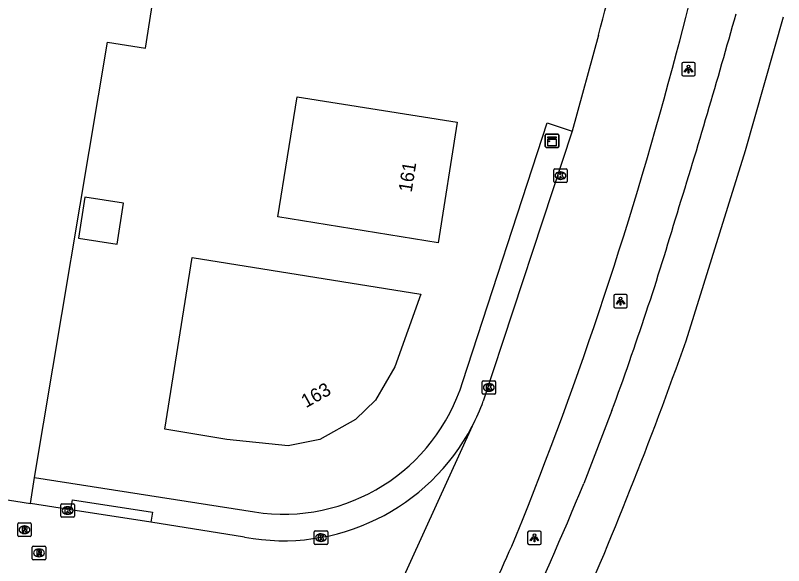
# Model space of a CAD drawing. Extents: x 154324 to 155743, y 382939 to 384183.
# Drawn here: x 155324.9 to 155381.7, y 383215.2 to 383256 of the extents above; entities that cross this region are included whole.
import ezdxf

# ---------------------------------------------------------------- set-up
doc = ezdxf.new("R2010")
doc.units = 0
for name, color, linetype in [('IMGEO_Fietspad_gesloten', 7, 'Continuous'), ('IMGEO_Groenvoorziening', 7, 'Continuous'), ('IMGEO_Kast', 7, 'Continuous'), ('IMGEO_Kolk', 7, 'Continuous'), ('IMGEO_Lichtpunt', 7, 'Continuous'), ('IMGEO_Pand', 7, 'Continuous'), ('IMGEO_Pand_nummerreeks', 7, 'Continuous'), ('IMGEO_Rijbaan_lokaal_gesloten', 7, 'Continuous'), ('IMGEO_Rijbaan_lokaal_open', 7, 'Continuous'), ('IMGEO_Rioolput', 7, 'Continuous'), ('IMGEO_Voetpad_open', 7, 'Continuous')]:
    doc.layers.add(name, color=color, linetype=linetype)

msp = doc.modelspace()

# ---------------------------------------------------------------- linework, layer by layer
at = {"layer": 'IMGEO_Fietspad_gesloten'}
for points in [[(155374.508, 383231.879), (155378.906, 383245.985), (155381.726, 383255.864)], [(155369.018, 383226.725), (155366.938, 383221.324)]]:
    msp.add_lwpolyline(points, dxfattribs=at)
for centre, radius, start, end in [((154859.102, 383401.381), 539.053, 342.73246, 344.36555), ((155146.238, 383308.495), 237.313, 339.84457, 343.56976), ((155076.293, 383337.641), 316.414, 336.21083, 340.473), ((155093.167, 383334.857), 296.379, 335.03919, 337.47613)]:
    msp.add_arc(centre, radius, start, end, dxfattribs=at)
at = {"layer": 'IMGEO_Groenvoorziening'}
msp.add_lwpolyline([(155326.27, 383221.771), (155331.676, 383253.994), (155334.487, 383253.554), (155341.319, 383297.286)], dxfattribs=at)
at = {"layer": 'IMGEO_Kast'}
for p, q in [((155364.086, 383246.27), (155364.086, 383247.111)), ((155364.086, 383247.111), (155364.086, 383246.27)), ((155364.161, 383247.195), (155365.002, 383247.195)), ((155365.002, 383247.195), (155364.161, 383247.195)), ((155365.086, 383247.12), (155365.086, 383246.279)), ((155365.086, 383246.279), (155365.086, 383247.12)), ((155365.011, 383246.195), (155364.17, 383246.195)), ((155364.17, 383246.195), (155365.011, 383246.195))]:
    msp.add_line(p, q, dxfattribs=at)
for points in [[(155364.281, 383246.985), (155364.881, 383246.985), (155364.881, 383246.9), (155364.281, 383246.9), (155364.281, 383246.985)], [(155364.281, 383246.81), (155364.881, 383246.81), (155364.881, 383246.321), (155364.281, 383246.321), (155364.281, 383246.81)]]:
    msp.add_lwpolyline(points, dxfattribs=at)
msp.add_circle((155364.365, 383246.659), 0.0377, dxfattribs=at)
for centre, start, end in [((155364.164, 383247.117), 92.4484, 184.2845), ((155364.164, 383247.117), 92.4484, 184.2845), ((155365.008, 383247.117), 2.4484, 94.2845), ((155365.008, 383247.117), 2.4484, 94.2845), ((155364.164, 383246.273), 182.4484, 274.2845), ((155364.164, 383246.273), 182.4484, 274.2845), ((155365.008, 383246.273), 272.4484, 4.2845), ((155365.008, 383246.273), 272.4484, 4.2845)]:
    msp.add_arc(centre, 0.0779, start, end, dxfattribs=at)
at = {"layer": 'IMGEO_Kolk'}
for p, q in [((155364.708, 383243.689), (155364.708, 383244.541)), ((155364.783, 383244.615), (155365.635, 383244.615)), ((155365.709, 383244.541), (155365.709, 383243.689)), ((155365.196, 383244.395), (155365.221, 383244.395)), ((155365.635, 383243.615), (155364.783, 383243.615)), ((155365.219, 383243.835), (155365.194, 383243.835)), ((155359.407, 383228.001), (155359.407, 383228.853)), ((155359.482, 383228.927), (155360.334, 383228.927)), ((155359.895, 383228.707), (155359.92, 383228.707)), ((155360.408, 383228.853), (155360.408, 383228.001)), ((155359.918, 383228.147), (155359.893, 383228.147)), ((155360.334, 383227.927), (155359.482, 383227.927)), ((155328.233, 383218.892), (155328.233, 383219.744)), ((155328.308, 383219.818), (155329.16, 383219.818)), ((155328.721, 383219.598), (155328.746, 383219.598)), ((155329.234, 383219.744), (155329.234, 383218.892)), ((155328.744, 383219.038), (155328.719, 383219.038)), ((155329.16, 383218.818), (155328.308, 383218.818)), ((155346.981, 383216.884), (155346.981, 383217.736)), ((155347.056, 383217.81), (155347.908, 383217.81)), ((155347.982, 383217.736), (155347.982, 383216.884)), ((155347.469, 383217.59), (155347.494, 383217.59)), ((155347.908, 383216.81), (155347.056, 383216.81)), ((155347.492, 383217.03), (155347.467, 383217.03))]:
    msp.add_line(p, q, dxfattribs=at)
for points in [[(155364.708, 383243.689), (155364.708, 383244.541)], [(155364.783, 383244.615), (155365.635, 383244.615)], [(155365.709, 383244.541), (155365.709, 383243.689)], [(155365.029, 383244.315), (155365.152, 383244.315), (155365.152, 383244.164), (155365.282, 383244.315), (155365.446, 383244.315), (155365.3, 383244.164), (155365.453, 383243.915), (155365.301, 383243.915), (155365.216, 383244.079), (155365.152, 383244.012), (155365.152, 383243.915), (155365.029, 383243.915), (155365.029, 383244.315)], [(155365.635, 383243.615), (155364.783, 383243.615)], [(155359.407, 383228.001), (155359.407, 383228.853)], [(155359.482, 383228.927), (155360.334, 383228.927)], [(155359.728, 383228.627), (155359.851, 383228.627), (155359.851, 383228.476), (155359.981, 383228.627), (155360.145, 383228.627), (155359.999, 383228.476), (155360.152, 383228.227), (155360, 383228.227), (155359.915, 383228.391), (155359.851, 383228.324), (155359.851, 383228.227), (155359.728, 383228.227), (155359.728, 383228.627)], [(155360.408, 383228.853), (155360.408, 383228.001)], [(155360.334, 383227.927), (155359.482, 383227.927)], [(155328.233, 383218.892), (155328.233, 383219.744)], [(155328.308, 383219.818), (155329.16, 383219.818)], [(155328.554, 383219.518), (155328.677, 383219.518), (155328.677, 383219.367), (155328.807, 383219.518), (155328.971, 383219.518), (155328.825, 383219.367), (155328.978, 383219.118), (155328.826, 383219.118), (155328.741, 383219.282), (155328.677, 383219.215), (155328.677, 383219.118), (155328.554, 383219.118), (155328.554, 383219.518)], [(155329.234, 383219.744), (155329.234, 383218.892)], [(155329.16, 383218.818), (155328.308, 383218.818)], [(155346.981, 383216.884), (155346.981, 383217.736)], [(155347.056, 383217.81), (155347.908, 383217.81)], [(155347.982, 383217.736), (155347.982, 383216.884)], [(155347.302, 383217.51), (155347.425, 383217.51), (155347.425, 383217.359), (155347.555, 383217.51), (155347.719, 383217.51), (155347.573, 383217.359), (155347.726, 383217.11), (155347.574, 383217.11), (155347.489, 383217.274), (155347.425, 383217.207), (155347.425, 383217.11), (155347.302, 383217.11), (155347.302, 383217.51)], [(155347.908, 383216.81), (155347.056, 383216.81)]]:
    msp.add_lwpolyline(points, dxfattribs=at)
for centre, start, end in [((155364.785, 383244.539), 91.552, 178.448), ((155364.785, 383244.539), 91.552, 178.448), ((155365.633, 383244.539), 1.552, 88.448), ((155365.633, 383244.539), 1.552, 88.448), ((155364.785, 383243.691), 181.552, 268.448), ((155364.785, 383243.691), 181.552, 268.448), ((155365.633, 383243.691), 271.552, 358.448), ((155365.633, 383243.691), 271.552, 358.448), ((155359.484, 383228.851), 91.552, 178.448), ((155359.484, 383228.851), 91.552, 178.448), ((155360.332, 383228.851), 1.552, 88.448), ((155360.332, 383228.851), 1.552, 88.448), ((155359.484, 383228.003), 181.552, 268.448), ((155359.484, 383228.003), 181.552, 268.448), ((155360.332, 383228.003), 271.552, 358.448), ((155360.332, 383228.003), 271.552, 358.448), ((155328.31, 383219.742), 91.552, 178.448), ((155328.31, 383219.742), 91.552, 178.448), ((155329.158, 383219.742), 1.552, 88.448), ((155329.158, 383219.742), 1.552, 88.448), ((155328.31, 383218.894), 181.552, 268.448), ((155328.31, 383218.894), 181.552, 268.448), ((155329.158, 383218.894), 271.552, 358.448), ((155329.158, 383218.894), 271.552, 358.448), ((155347.058, 383217.734), 91.552, 178.448), ((155347.058, 383217.734), 91.552, 178.448), ((155347.906, 383217.734), 1.552, 88.448), ((155347.906, 383217.734), 1.552, 88.448), ((155347.058, 383216.886), 181.552, 268.448), ((155347.058, 383216.886), 181.552, 268.448), ((155347.906, 383216.886), 271.552, 358.448), ((155347.906, 383216.886), 271.552, 358.448)]:
    msp.add_arc(centre, 0.0765, start, end, dxfattribs=at)
for centre, major_axis, ratio, start_param, end_param in [((155365.195, 383244.115), (-0.387, 0.002), 0.722429, 4.712389, 7.853982), ((155365.22, 383244.115), (-0.39, 0.002), 0.717154, 1.570796, 4.712389), ((155359.894, 383228.427), (-0.387, 0.002), 0.722429, 4.712389, 7.853982), ((155359.919, 383228.427), (-0.39, 0.002), 0.717154, 1.570796, 4.712389), ((155328.72, 383219.318), (-0.387, 0.002), 0.722429, 4.712389, 7.853982), ((155328.745, 383219.318), (-0.39, 0.002), 0.717154, 1.570796, 4.712389), ((155347.468, 383217.31), (-0.387, 0.002), 0.722429, 4.712389, 7.853982), ((155347.493, 383217.31), (-0.39, 0.002), 0.717154, 1.570796, 4.712389)]:
    msp.add_ellipse(centre, major_axis=major_axis, ratio=ratio, start_param=start_param, end_param=end_param, dxfattribs=at)
at = {"layer": 'IMGEO_Lichtpunt'}
for p, q in [((155375.087, 383252.498), (155374.279, 383252.498)), ((155375.087, 383252.498), (155374.279, 383252.498)), ((155374.185, 383252.403), (155374.185, 383251.596)), ((155374.185, 383252.403), (155374.185, 383251.596)), ((155375.181, 383251.596), (155375.181, 383252.403)), ((155375.181, 383251.596), (155375.181, 383252.403)), ((155374.279, 383251.502), (155375.087, 383251.502)), ((155374.279, 383251.502), (155375.087, 383251.502)), ((155369.156, 383235.228), (155369.156, 383234.421)), ((155369.156, 383235.228), (155369.156, 383234.421)), ((155370.058, 383235.323), (155369.25, 383235.323)), ((155370.058, 383235.323), (155369.25, 383235.323)), ((155370.152, 383234.421), (155370.152, 383235.228)), ((155370.152, 383234.421), (155370.152, 383235.228)), ((155369.25, 383234.327), (155370.058, 383234.327)), ((155369.25, 383234.327), (155370.058, 383234.327)), ((155363.681, 383217.798), (155362.873, 383217.798)), ((155363.681, 383217.798), (155362.873, 383217.798)), ((155362.779, 383217.703), (155362.779, 383216.896)), ((155362.779, 383217.703), (155362.779, 383216.896)), ((155363.775, 383216.896), (155363.775, 383217.703)), ((155363.775, 383216.896), (155363.775, 383217.703)), ((155362.873, 383216.802), (155363.681, 383216.802)), ((155362.873, 383216.802), (155363.681, 383216.802))]:
    msp.add_line(p, q, dxfattribs=at)
for points in [[(155374.559, 383252.067), (155374.598, 383252.039), (155374.41, 383251.777), (155374.372, 383251.804), (155374.559, 383252.067)], [(155374.661, 383252.019), (155374.708, 383252.019), (155374.708, 383251.697), (155374.661, 383251.697), (155374.661, 383252.019)], [(155374.771, 383252.039), (155374.809, 383252.066), (155374.996, 383251.804), (155374.957, 383251.776), (155374.771, 383252.039)], [(155369.53, 383234.892), (155369.569, 383234.864), (155369.381, 383234.602), (155369.343, 383234.629), (155369.53, 383234.892)], [(155369.632, 383234.844), (155369.679, 383234.844), (155369.679, 383234.522), (155369.632, 383234.522), (155369.632, 383234.844)], [(155369.742, 383234.864), (155369.78, 383234.891), (155369.967, 383234.629), (155369.928, 383234.601), (155369.742, 383234.864)], [(155363.153, 383217.367), (155363.192, 383217.339), (155363.004, 383217.077), (155362.966, 383217.104), (155363.153, 383217.367)], [(155363.255, 383217.319), (155363.302, 383217.319), (155363.302, 383216.997), (155363.255, 383216.997), (155363.255, 383217.319)], [(155363.365, 383217.339), (155363.403, 383217.366), (155363.59, 383217.104), (155363.551, 383217.076), (155363.365, 383217.339)]]:
    msp.add_lwpolyline(points, dxfattribs=at)
for centre in [(155374.684, 383252.201), (155369.655, 383235.026), (155363.278, 383217.501)]:
    msp.add_circle(centre, 0.0994, dxfattribs=at)
for centre, start, end in [((155374.279, 383252.403), 90, 180), ((155374.279, 383252.403), 90, 180), ((155375.087, 383252.403), 0, 90), ((155375.087, 383252.403), 0, 90), ((155374.279, 383251.596), 180, 270), ((155374.279, 383251.596), 180, 270), ((155375.087, 383251.596), 270, 0), ((155375.087, 383251.596), 270, 360), ((155369.25, 383235.228), 90, 180), ((155369.25, 383235.228), 90, 180), ((155370.058, 383235.228), 0, 90), ((155370.058, 383235.228), 0, 90), ((155369.25, 383234.421), 180, 270), ((155369.25, 383234.421), 180, 270), ((155370.058, 383234.421), 270, 0), ((155370.058, 383234.421), 270, 360), ((155362.873, 383217.703), 90, 180), ((155362.873, 383217.703), 90, 180), ((155363.681, 383217.703), 0, 90), ((155363.681, 383217.703), 0, 90), ((155362.873, 383216.896), 180, 270), ((155362.873, 383216.896), 180, 270), ((155363.681, 383216.896), 270, 0), ((155363.681, 383216.896), 270, 360)]:
    msp.add_arc(centre, 0.0946, start, end, dxfattribs=at)
at = {"layer": 'IMGEO_Pand'}
for points in [[(155357.573, 383248.067), (155356.157, 383239.149), (155344.285, 383241.069), (155345.717, 383249.958), (155357.573, 383248.067)], [(155329.989, 383242.521), (155329.521, 383239.482), (155332.387, 383239.041), (155332.855, 383242.08), (155329.989, 383242.521)], [(155354.881, 383235.351), (155352.935, 383229.965), (155351.515, 383227.488), (155350.034, 383226.048), (155347.398, 383224.581), (155345.061, 383224.111), (155340.504, 383224.574), (155335.916, 383225.332), (155337.937, 383238.063), (155354.881, 383235.351)]]:
    msp.add_lwpolyline(points, dxfattribs=at)
at = {"layer": 'IMGEO_Rijbaan_lokaal_gesloten'}
for points in [[(155368.018, 383254.513), (155366.082, 383247.416)], [(155366.082, 383247.416), (155359.493, 383227.412)], [(155358.678, 383225.57), (155351.45, 383209.687)]]:
    msp.add_lwpolyline(points, dxfattribs=at)
for centre, radius, start, end in [((154920.161, 383375.05), 469.711, 344.96734, 348.48239), ((154771.317, 383413.289), 617.464, 345.099417, 346.959795), ((155088.644, 383327.943), 294.78, 338.00066, 345.31634), ((155344.714, 383232.85), 15.748, 332.4661, 339.7996), ((155185.355, 383294.013), 192.46, 334.42002, 336.58102)]:
    msp.add_arc(centre, radius, start, end, dxfattribs=at)
at = {"layer": 'IMGEO_Rijbaan_lokaal_open'}
for points in [[(155210.474, 383238.238), (155325.977, 383219.831)], [(155328.96, 383219.381), (155325.977, 383219.831)], [(155334.892, 383218.461), (155328.96, 383219.381)], [(155341.812, 383217.346), (155334.892, 383218.461)]]:
    msp.add_lwpolyline(points, dxfattribs=at)
msp.add_arc((155344.683, 383232.864), 15.781, 259.5164, 332.472, dxfattribs=at)
at = {"layer": 'IMGEO_Rioolput'}
for p, q in [((155325.034, 383217.47), (155325.034, 383218.322)), ((155325.109, 383218.396), (155325.961, 383218.396)), ((155326.035, 383218.322), (155326.035, 383217.47)), ((155325.522, 383218.176), (155325.547, 383218.176)), ((155325.961, 383217.396), (155325.109, 383217.396)), ((155325.545, 383217.616), (155325.52, 383217.616)), ((155326.11, 383215.753), (155326.11, 383216.605)), ((155326.185, 383216.679), (155327.037, 383216.679)), ((155327.111, 383216.605), (155327.111, 383215.753)), ((155326.598, 383216.459), (155326.623, 383216.459)), ((155327.037, 383215.679), (155326.185, 383215.679)), ((155326.621, 383215.899), (155326.596, 383215.899))]:
    msp.add_line(p, q, dxfattribs=at)
for points in [[(155325.034, 383217.47), (155325.034, 383218.322)], [(155325.109, 383218.396), (155325.961, 383218.396)], [(155326.035, 383218.322), (155326.035, 383217.47)], [(155325.623, 383218.094), (155325.371, 383218.096), (155325.371, 383217.696)], [(155325.371, 383217.696), (155325.495, 383217.696), (155325.495, 383217.858), (155325.506, 383217.858)], [(155325.549, 383218.015), (155325.495, 383218.015), (155325.495, 383217.934)], [(155325.495, 383217.934), (155325.547, 383217.934)], [(155325.553, 383217.829), (155325.624, 383217.696), (155325.764, 383217.696), (155325.699, 383217.822)], [(155325.961, 383217.396), (155325.109, 383217.396)], [(155326.11, 383215.753), (155326.11, 383216.605)], [(155326.185, 383216.679), (155327.037, 383216.679)], [(155327.111, 383216.605), (155327.111, 383215.753)], [(155326.699, 383216.377), (155326.447, 383216.379), (155326.447, 383215.979)], [(155326.447, 383215.979), (155326.571, 383215.979), (155326.571, 383216.141), (155326.582, 383216.141)], [(155326.625, 383216.298), (155326.571, 383216.298), (155326.571, 383216.217)], [(155326.571, 383216.217), (155326.623, 383216.217)], [(155326.629, 383216.112), (155326.7, 383215.979), (155326.84, 383215.979), (155326.775, 383216.105)], [(155327.037, 383215.679), (155326.185, 383215.679)]]:
    msp.add_lwpolyline(points, dxfattribs=at)
for centre, radius, start, end in [((155325.111, 383218.32), 0.0765, 91.552, 178.448), ((155325.111, 383218.32), 0.0765, 91.552, 178.448), ((155325.959, 383218.32), 0.0765, 1.552, 88.448), ((155325.959, 383218.32), 0.0765, 1.552, 88.448), ((155325.505, 383217.805), 0.0533, 26.0293, 88.6989), ((155325.531, 383218.123), 0.19, 274.7715, 282.9687), ((155325.555, 383217.919), 0.0964, 77.0061, 93.1865), ((155325.569, 383217.976), 0.0378, 276.6634, 79.6772), ((155325.622, 383217.984), 0.109, 350.3612, 89.416), ((155325.62, 383217.984), 0.112, 277.5842, 350.9817), ((155325.604, 383217.769), 0.108, 29.5134, 73.7905), ((155325.111, 383217.472), 0.0765, 181.552, 268.448), ((155325.111, 383217.472), 0.0765, 181.552, 268.448), ((155325.959, 383217.472), 0.0765, 271.552, 358.448), ((155325.959, 383217.472), 0.0765, 271.552, 358.448), ((155326.187, 383216.603), 0.0765, 91.552, 178.448), ((155326.187, 383216.603), 0.0765, 91.552, 178.448), ((155327.035, 383216.603), 0.0765, 1.552, 88.448), ((155327.035, 383216.603), 0.0765, 1.552, 88.448), ((155326.581, 383216.088), 0.0533, 26.0293, 88.6989), ((155326.607, 383216.406), 0.19, 274.7715, 282.9687), ((155326.631, 383216.202), 0.0964, 77.0061, 93.1865), ((155326.645, 383216.259), 0.0378, 276.6634, 79.6772), ((155326.698, 383216.267), 0.109, 350.3612, 89.416), ((155326.696, 383216.267), 0.112, 277.5842, 350.9817), ((155326.68, 383216.052), 0.108, 29.5134, 73.7905), ((155326.187, 383215.755), 0.0765, 181.552, 268.448), ((155326.187, 383215.755), 0.0765, 181.552, 268.448), ((155327.035, 383215.755), 0.0765, 271.552, 358.448), ((155327.035, 383215.755), 0.0765, 271.552, 358.448)]:
    msp.add_arc(centre, radius, start, end, dxfattribs=at)
for centre, major_axis, ratio, start_param, end_param in [((155325.521, 383217.896), (-0.387, 0.002), 0.722429, 4.712389, 7.853982), ((155325.546, 383217.896), (-0.39, 0.002), 0.717154, 1.570796, 4.712389), ((155326.597, 383216.179), (-0.387, 0.002), 0.722429, 4.712389, 7.853982), ((155326.622, 383216.179), (-0.39, 0.002), 0.717154, 1.570796, 4.712389)]:
    msp.add_ellipse(centre, major_axis=major_axis, ratio=ratio, start_param=start_param, end_param=end_param, dxfattribs=at)
at = {"layer": 'IMGEO_Voetpad_open'}
for points in [[(155357.974, 383228.876), (155364.232, 383248.015), (155366.082, 383247.416)], [(155325.977, 383219.831), (155326.27, 383221.771)], [(155326.27, 383221.771), (155342.552, 383219.211)], [(155328.96, 383219.381), (155329.085, 383220.106), (155335.017, 383219.189), (155334.892, 383218.461)]]:
    msp.add_lwpolyline(points, dxfattribs=at)
msp.add_arc((155344.687, 383232.94), 13.894, 261.1588, 342.9921, dxfattribs=at)

# ---------------------------------------------------------------- texts
at = {"layer": 'IMGEO_Pand_nummerreeks'}
for s, rotation, p in [('161', 80.9785, (155354.192, 383242.844)), ('163', 29.0842, (155346.369, 383226.892))]:
    msp.add_text(s, height=1, rotation=rotation, dxfattribs=at).set_placement(p)

doc.saveas('drawing.dxf')
